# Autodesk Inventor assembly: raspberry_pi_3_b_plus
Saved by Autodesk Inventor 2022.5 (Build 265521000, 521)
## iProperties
Created: 2024-12
Part Number: raspberry_pi_3_b_plus
Document SubType Name: Assembly
Designer: AdminForWorker
Title: raspberry_pi_3_b_plus v1
Author: AdminForWorker
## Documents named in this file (34)
- c:\worker\convert-fusion-r05-cosv3\tmp\job-1\35\temp\files\545dca92-a972-481a-9197-dd1a1176500e\raspberry_pi_3_b_plus v1.iam
- c:\worker\convert-fusion-r05-cosv3\tmp\job-1\35\temp\files\545dca92-a972-481a-9197-dd1a1176500e\pcb.ipt
- c:\worker\convert-fusion-r05-cosv3\tmp\job-1\35\temp\files\545dca92-a972-481a-9197-dd1a1176500e\micro_usb_connector v17.iam
- c:\worker\convert-fusion-r05-cosv3\tmp\job-1\35\temp\files\545dca92-a972-481a-9197-dd1a1176500e\sd_card_slot_molex v11.iam
- c:\worker\convert-fusion-r05-cosv3\tmp\job-1\35\temp\files\545dca92-a972-481a-9197-dd1a1176500e\USB-A-stack-1x2 v1.iam
- c:\worker\convert-fusion-r05-cosv3\tmp\job-1\35\temp\files\545dca92-a972-481a-9197-dd1a1176500e\USB-A-stack-1x2 v1_1.iam
- c:\worker\convert-fusion-r05-cosv3\tmp\job-1\35\temp\files\545dca92-a972-481a-9197-dd1a1176500e\Pin Header 20x2 TH Pitch 2.54mm v1.iam
- c:\worker\convert-fusion-r05-cosv3\tmp\job-1\35\temp\files\545dca92-a972-481a-9197-dd1a1176500e\Pin Header 2x2 TH Pitch 2.54mm v1.iam
- c:\worker\convert-fusion-r05-cosv3\tmp\job-1\35\temp\files\545dca92-a972-481a-9197-dd1a1176500e\te_1-1734248-5.ipt
- c:\worker\convert-fusion-r05-cosv3\tmp\job-1\35\temp\files\545dca92-a972-481a-9197-dd1a1176500e\EDAC_1743_RJ45_TH v1.iam
- c:\worker\convert-fusion-r05-cosv3\tmp\job-1\35\temp\files\545dca92-a972-481a-9197-dd1a1176500e\SOP-3_1.6mm.ipt
- c:\worker\convert-fusion-r05-cosv3\tmp\job-1\35\temp\files\545dca92-a972-481a-9197-dd1a1176500e\qfn32_5mm v1.ipt
- c:\worker\convert-fusion-r05-cosv3\tmp\job-1\35\temp\files\545dca92-a972-481a-9197-dd1a1176500e\qfn48_9mm v1.ipt
- c:\worker\convert-fusion-r05-cosv3\tmp\job-1\35\temp\files\545dca92-a972-481a-9197-dd1a1176500e\TSOP-6 2mm v1.ipt
- c:\worker\convert-fusion-r05-cosv3\tmp\job-1\35\temp\files\545dca92-a972-481a-9197-dd1a1176500e\TSOP-6 3mm v1.ipt
- c:\worker\convert-fusion-r05-cosv3\tmp\job-1\35\temp\files\545dca92-a972-481a-9197-dd1a1176500e\qfp16_3x2mm v1.iam
- c:\worker\convert-fusion-r05-cosv3\tmp\job-1\35\temp\files\545dca92-a972-481a-9197-dd1a1176500e\qfn80_12mm v1.ipt
- c:\worker\convert-fusion-r05-cosv3\tmp\job-1\35\temp\files\545dca92-a972-481a-9197-dd1a1176500e\crystal_dfn4 v1.iam
- c:\worker\convert-fusion-r05-cosv3\tmp\job-1\35\temp\files\545dca92-a972-481a-9197-dd1a1176500e\bcm2837 v1.ipt
- c:\worker\convert-fusion-r05-cosv3\tmp\job-1\35\temp\files\545dca92-a972-481a-9197-dd1a1176500e\wlbga140_5mm v1.ipt
- c:\worker\convert-fusion-r05-cosv3\tmp\job-1\35\temp\files\545dca92-a972-481a-9197-dd1a1176500e\wifi.iam
- c:\worker\convert-fusion-r05-cosv3\tmp\job-1\35\temp\files\545dca92-a972-481a-9197-dd1a1176500e\cap0603_03 v1.ipt
- c:\worker\convert-fusion-r05-cosv3\tmp\job-1\35\temp\files\545dca92-a972-481a-9197-dd1a1176500e\cap0402 v1.ipt
- c:\worker\convert-fusion-r05-cosv3\tmp\job-1\35\temp\files\545dca92-a972-481a-9197-dd1a1176500e\resistor_0402 v1.ipt
- c:\worker\convert-fusion-r05-cosv3\tmp\job-1\35\temp\files\545dca92-a972-481a-9197-dd1a1176500e\cap1206 v1.ipt
- c:\worker\convert-fusion-r05-cosv3\tmp\job-1\35\temp\files\545dca92-a972-481a-9197-dd1a1176500e\ind2520 v1.ipt
- c:\worker\convert-fusion-r05-cosv3\tmp\job-1\35\temp\files\545dca92-a972-481a-9197-dd1a1176500e\ledra_0603 v1.ipt
- c:\worker\convert-fusion-r05-cosv3\tmp\job-1\35\temp\files\545dca92-a972-481a-9197-dd1a1176500e\pj-322 v1.iam
- c:\worker\convert-fusion-r05-cosv3\tmp\job-1\35\temp\files\545dca92-a972-481a-9197-dd1a1176500e\SOP-3 v1.ipt
- c:\worker\convert-fusion-r05-cosv3\tmp\job-1\35\temp\files\545dca92-a972-481a-9197-dd1a1176500e\SOP-3 2.5mm v1.ipt
- c:\worker\convert-fusion-r05-cosv3\tmp\job-1\35\temp\files\545dca92-a972-481a-9197-dd1a1176500e\capar2_1013 v1.ipt
- c:\worker\convert-fusion-r05-cosv3\tmp\job-1\35\temp\files\545dca92-a972-481a-9197-dd1a1176500e\molex hdmi smt v1.iam
- c:\worker\convert-fusion-r05-cosv3\tmp\job-1\35\temp\files\545dca92-a972-481a-9197-dd1a1176500e\TSOP-2 4mm v1.ipt
- c:\worker\convert-fusion-r05-cosv3\tmp\job-1\35\temp\files\545dca92-a972-481a-9197-dd1a1176500e\SMD PTC Fuse MF-MSMF250_16X v1.ipt
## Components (239 placed, 33 different names)
1. pcb:1
2. micro_usb_connector v17:1 [sub-assembly]
3. sd_card_slot_molex v11:1 [sub-assembly]
4. USB-A-stack-1x2 v1:1 [sub-assembly]
5. USB-A-stack-1x2 v1:2 [sub-assembly]
6. Pin Header 20x2 TH Pitch 2.54mm v1:1 [sub-assembly]
7. Pin Header 2x2 TH Pitch 2.54mm v1:1 [sub-assembly]
8. te_1-1734248-5:1
9. te_1-1734248-5:2
10. EDAC_1743_RJ45_TH v1:1 [sub-assembly]
11. SOP-3_1.6mm:1
12. SOP-3_1.6mm:1:1
13. SOP-3_1.6mm:2
14. SOP-3_1.6mm:3
15. qfn32_5mm v1:1
16. qfn48_9mm v1:1
17. TSOP-6 2mm v1:1
18. TSOP-6 3mm v1:1
19. qfp16_3x2mm v1:1 [sub-assembly]
20. qfn80_12mm v1:1
21. crystal_dfn4 v1:1 [sub-assembly]
22. bcm2837 v1:1
23. wlbga140_5mm v1:1
24. wifi:1 [sub-assembly]
25. cap0603_03 v1:1
26. cap0603_03 v1:2
27. cap0603_03 v1:3
28. cap0603_03 v1:4
29. cap0603_03 v1:5
30. cap0603_03 v1:6
31. cap0603_03 v1:7
32. cap0603_03 v1:8
33. cap0402 v1:1
34. cap0402 v1:2
35. cap0402 v1:3
36. cap0402 v1:4
37. cap0402 v1:5
38. cap0402 v1:6
39. cap0402 v1:7
40. cap0402 v1:8
41. cap0402 v1:9
42. cap0402 v1:10
43. cap0402 v1:11
44. cap0402 v1:12
45. cap0402 v1:13
46. cap0402 v1:14
47. cap0402 v1:15
48. cap0402 v1:16
49. cap0402 v1:17
50. cap0402 v1:18
51. cap0402 v1:19
52. cap0402 v1:20
53. cap0402 v1:21
54. cap0402 v1:22
55. cap0402 v1:23
56. cap0402 v1:24
57. cap0402 v1:25
58. cap0402 v1:26
59. cap0402 v1:27
60. cap0402 v1:28
61. cap0402 v1:29
62. cap0402 v1:30
63. cap0402 v1:31
64. cap0402 v1:32
65. cap0402 v1:33
66. cap0402 v1:34
67. cap0402 v1:35
68. cap0402 v1:36
69. cap0402 v1:37
70. resistor_0402 v1:1
71. resistor_0402 v1:2
72. resistor_0402 v1:3
73. resistor_0402 v1:4
74. resistor_0402 v1:5
75. cap0402 v1:38
76. cap0402 v1:39
77. resistor_0402 v1:6
78. cap0402 v1:40
79. cap0402 v1:41
80. resistor_0402 v1:7
81. resistor_0402 v1:8
82. resistor_0402 v1:9
83. resistor_0402 v1:10
84. resistor_0402 v1:11
85. resistor_0402 v1:12
86. resistor_0402 v1:13
87. resistor_0402 v1:14
88. resistor_0402 v1:15
89. resistor_0402 v1:16
90. resistor_0402 v1:17
91. resistor_0402 v1:18
92. resistor_0402 v1:19
93. resistor_0402 v1:20
94. resistor_0402 v1:21
95. resistor_0402 v1:22
96. resistor_0402 v1:23
97. resistor_0402 v1:24
98. resistor_0402 v1:25
99. resistor_0402 v1:26
100. resistor_0402 v1:27
101. resistor_0402 v1:28
102. resistor_0402 v1:29
103. resistor_0402 v1:30
104. resistor_0402 v1:31
105. resistor_0402 v1:32
106. resistor_0402 v1:33
107. resistor_0402 v1:34
108. resistor_0402 v1:35
109. resistor_0402 v1:36
110. resistor_0402 v1:37
111. resistor_0402 v1:38
112. cap0402 v1:42
113. resistor_0402 v1:39
114. resistor_0402 v1:40
115. cap1206 v1:1
116. cap1206 v1:2
117. cap1206 v1:3
118. cap1206 v1:4
119. cap1206 v1:5
120. cap1206 v1:6
121. cap1206 v1:7
122. cap1206 v1:8
123. cap1206 v1:9
124. cap1206 v1:10
125. cap1206 v1:11
126. cap0603_03 v1:9
127. cap0603_03 v1:10
128. cap0603_03 v1:11
129. cap0603_03 v1:12
130. cap0603_03 v1:13
131. cap0603_03 v1:14
132. cap0603_03 v1:15
133. crystal_dfn4 v1:2 [sub-assembly]
134. resistor_0402 v1:41
135. resistor_0402 v1:42
136. resistor_0402 v1:43
137. resistor_0402 v1:44
138. resistor_0402 v1:45
139. resistor_0402 v1:46
140. resistor_0402 v1:47
141. resistor_0402 v1:48
142. resistor_0402 v1:49
143. resistor_0402 v1:50
144. resistor_0402 v1:51
145. resistor_0402 v1:52
146. resistor_0402 v1:53
147. resistor_0402 v1:54
148. resistor_0402 v1:55
149. resistor_0402 v1:56
150. resistor_0402 v1:57
151. cap0402 v1:43
152. cap0402 v1:44
153. cap0402 v1:45
154. cap0402 v1:46
155. ind2520 v1:1
156. ind2520 v1:2
157. ind2520 v1:3
158. ind2520 v1:4
159. ledra_0603 v1:1
160. ledra_0603 v1:2
161. pj-322 v1:1 [sub-assembly]
162. SOP-3 v1:1
163. SOP-3 2.5mm v1:1
164. capar2_1013 v1:1
165. capar2_1013 v1:2
166. capar2_1013 v1:3
167. capar2_1013 v1:4
168. molex hdmi smt v1:1 [sub-assembly]
169. TSOP-2 4mm v1:1
170. cap0402 v1:47
171. cap0402 v1:48
172. cap0402 v1:49
173. cap0402 v1:50
174. cap0402 v1:51
175. cap0402 v1:52
176. cap0402 v1:53
177. cap0402 v1:54
178. cap0402 v1:55
179. cap0402 v1:56
180. cap0402 v1:57
181. cap0402 v1:58
182. cap0402 v1:59
183. cap0402 v1:60
184. cap0402 v1:61
185. cap0402 v1:62
186. cap0402 v1:63
187. cap0402 v1:64
188. cap0402 v1:65
189. cap0402 v1:66
190. cap0402 v1:67
191. cap0402 v1:68
192. cap0402 v1:69
193. cap0402 v1:70
194. cap0402 v1:71
195. cap0402 v1:72
196. cap0402 v1:73
197. cap0402 v1:74
198. cap0402 v1:75
199. cap0402 v1:76
200. cap0402 v1:77
201. cap0402 v1:78
202. cap0402 v1:79
203. cap0402 v1:80
204. cap0402 v1:81
205. cap0402 v1:82
206. cap0402 v1:83
207. cap0402 v1:84
208. cap0402 v1:85
209. cap0402 v1:86
210. cap0402 v1:87
211. cap0402 v1:88
212. cap0402 v1:89
213. cap0402 v1:90
214. SMD PTC Fuse MF-MSMF250_16X v1:1
215. cap0402 v1:91
216. cap0402 v1:92
217. cap0402 v1:93
218. cap0402 v1:94
219. cap0402 v1:95
220. cap0402 v1:96
221. cap0402 v1:97
222. cap0402 v1:98
223. cap0402 v1:99
224. cap0402 v1:100
225. cap0402 v1:101
226. cap0402 v1:102
227. cap0402 v1:103
228. cap0402 v1:104
229. cap0402 v1:105
230. cap0402 v1:106
231. cap0402 v1:107
232. cap0402 v1:108
233. cap0402 v1:109
234. cap0402 v1:110
235. cap0402 v1:111
236. cap0402 v1:112
237. cap0402 v1:113
238. cap0402 v1:114
239. cap0402 v1:115
